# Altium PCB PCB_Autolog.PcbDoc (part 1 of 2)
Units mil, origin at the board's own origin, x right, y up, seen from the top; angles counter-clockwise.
Board outline 3847.36 x 2641.73 mil, 2 copper layers (Top Layer, Bottom Layer); 80 components, 62 nets, 278 pads, 180 vias.
Unrouted connection lines stored in the file: 64.
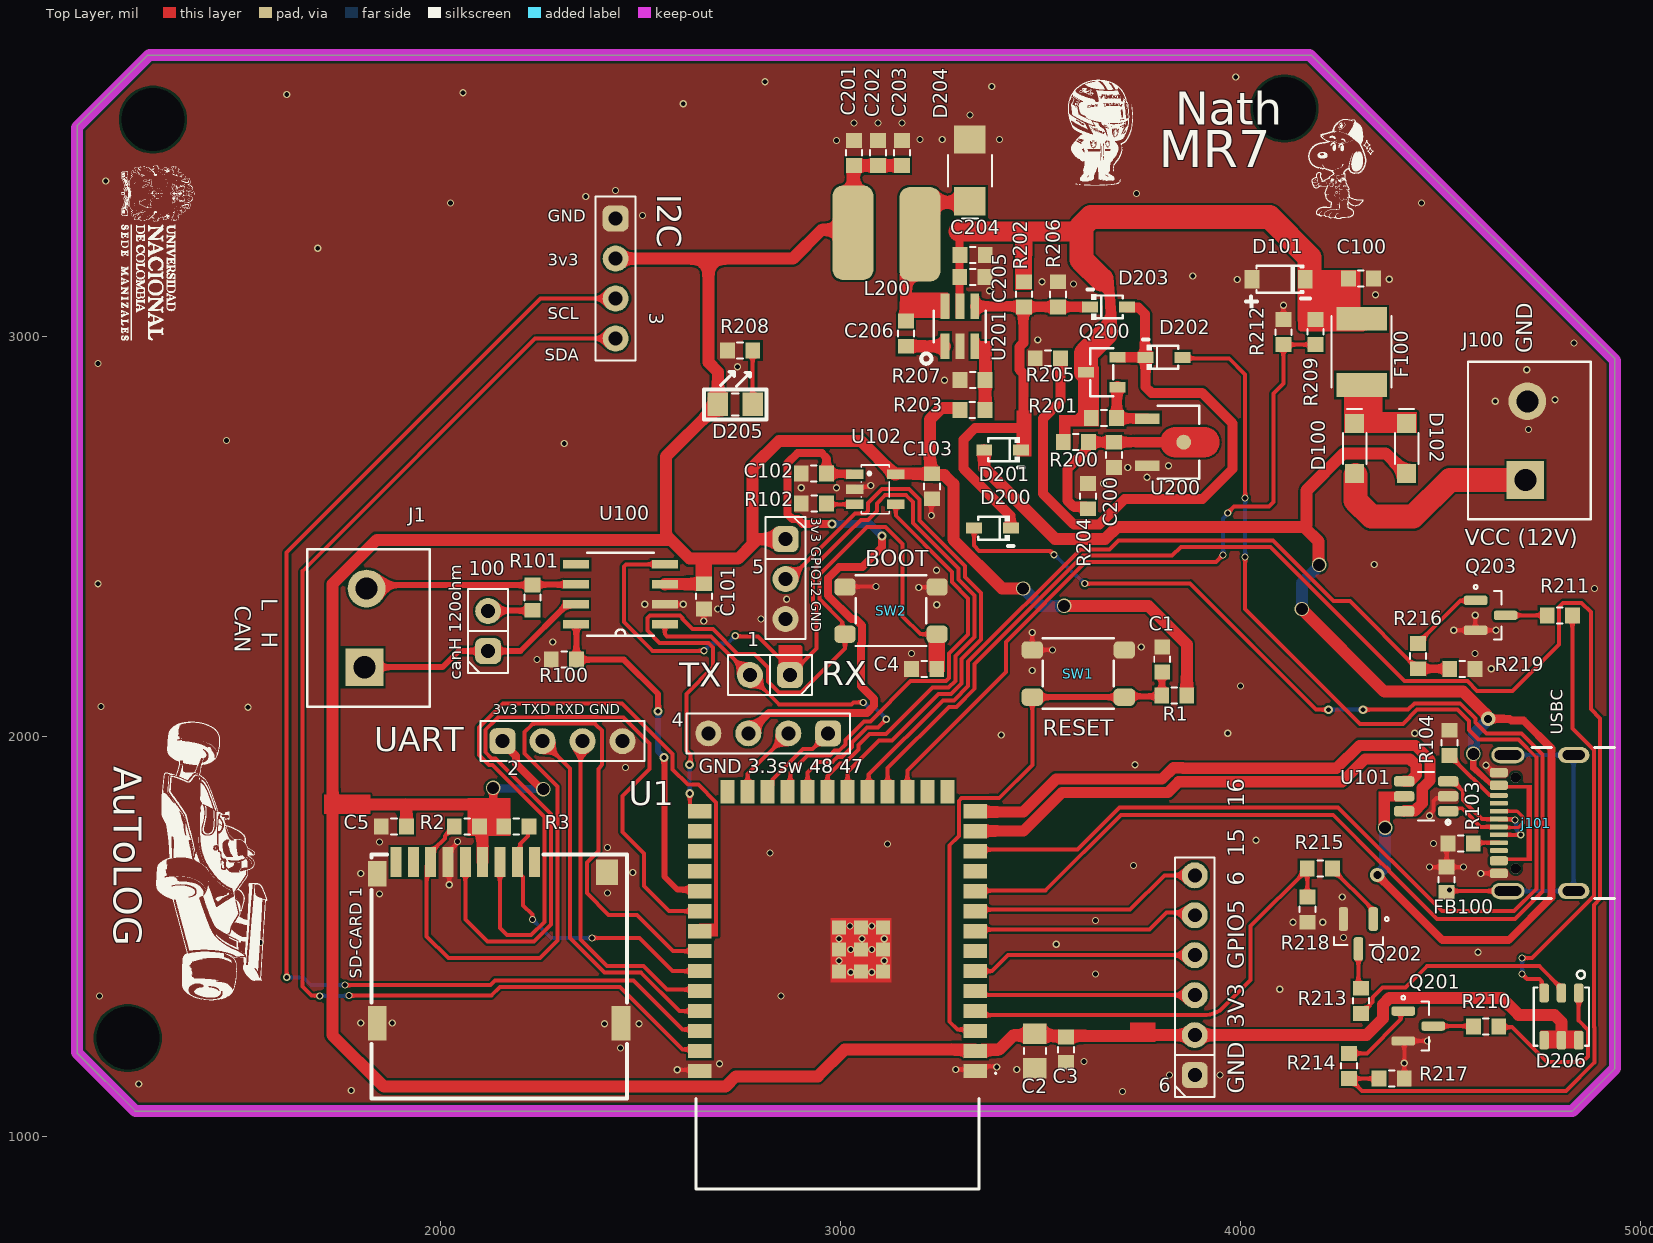
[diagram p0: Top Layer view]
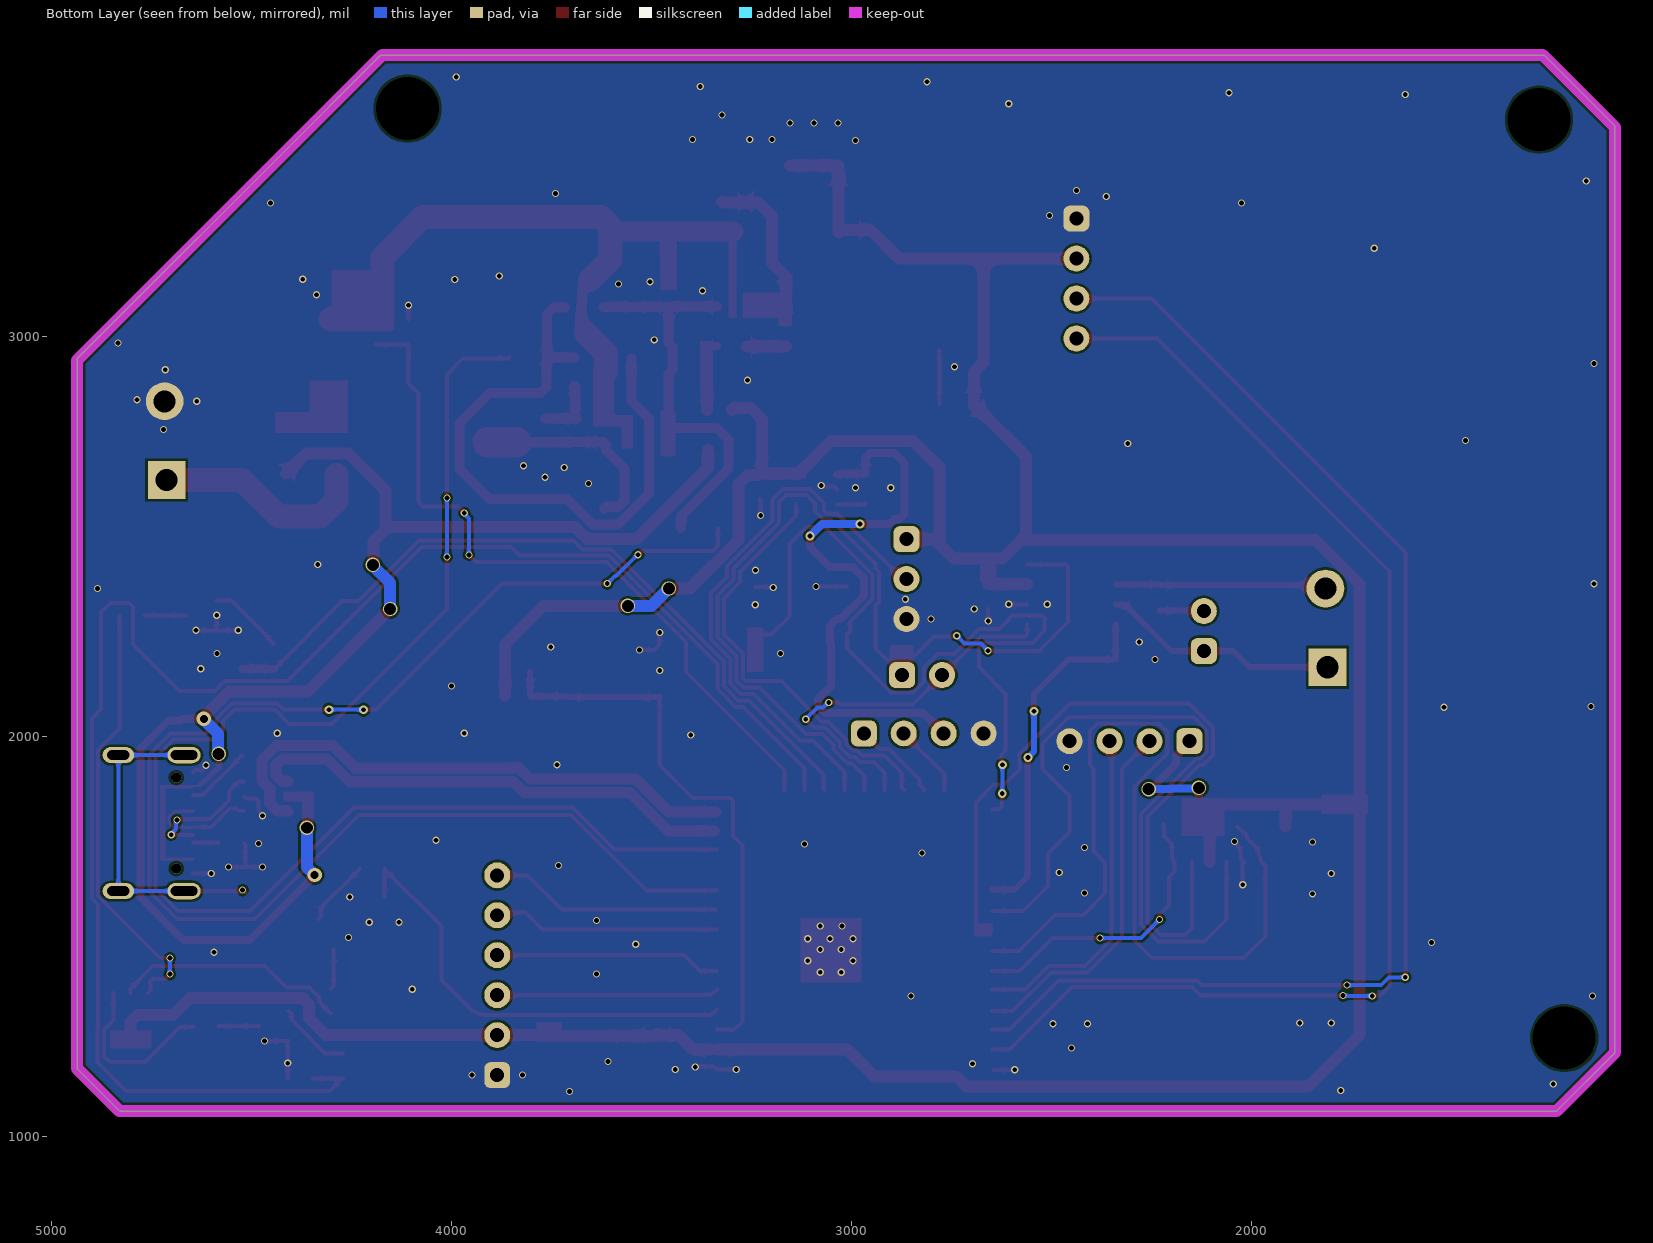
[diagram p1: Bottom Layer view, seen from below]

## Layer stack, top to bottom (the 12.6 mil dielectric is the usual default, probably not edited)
Top Solder: solder mask 0.4, Solder Resist, Dk 3.5
Top Layer: signal copper 1.4
Dielectric 1: dielectric 12.6, FR-4, Dk 4.8
Bottom Layer: signal copper 1.4
Bottom Solder: solder mask 0.4, Solder Resist, Dk 3.5

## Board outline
1089.65,1209.01 1235.67,1062.99 4830.71,1062.99 4937.01,1169.29 4937.01,2944.88 4826.77,3055.12 4437.01,3444.88 4177.17,3704.72 1266.95,3704.72 1089.65,3527.42

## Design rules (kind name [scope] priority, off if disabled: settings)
Clearance Clearance_1 [All] p1: gap=6 ignorepadtopadclearanceinfootprint=FALSE
Clearance Clearance_Vias [isvia] p2: gap=0 ignorepadtopadclearanceinfootprint=FALSE
DiffPairsRouting [All] p1: maxlimit=6 minlimit=6 mostfreqgap=6 toplayer_minwidth=10 toplayer_maxwidth=28 toplayer_prefwidth=28 bottomlayer_minwidth=10 bottomlayer_maxwidth=28 bottomlayer_prefwidth=28 maxuncoupledlength=500
HoleSize [All] p1: absolutevalues=TRUE maxlimit=200 minlimit=12 maxpercent=80.000 minpercent=20.000
MinimumAnnularRing [All] p1: minimumring=3
MinimumSolderMaskSliver [All] p1: minsoldermaskwidth=4
PlaneConnect [All] p1: planeconnectstyle=Direct reliefexpansion=20 reliefentries=4 reliefconductorwidth=10 reliefairgap=10
PolygonConnect [All] p1: connectstyle=Direct reliefconductorwidth=8 reliefentries=4 polygonreliefangle="90 Angle" airgapwidth=6
RoutingVias [All] p1: holewidth=12 width=22 viastyle="Through Hole" minholewidth=12 minwidth=18 maxholewidth=30 maxwidth=40
SilkToSilkClearance [All] p1: silktosilkclearance=2
SilkToSolderMaskClearance [IsPad] p1: minsilkscreentomaskgap=0.1 clearancetoexposedcopper=TRUE
SolderMaskExpansion SolderMaskExpansion_via [IsVia] p1: expansion=2 istentingtop=TRUE
SolderMaskExpansion [All] p2: expansion=2 istentingtop=FALSE
SupplyNets "Schematic Supply Nets_2" [InNet('3V3')] p1: voltage=0.000
SupplyNets "Schematic Supply Nets_1" [InNet('VCC')] p2: voltage=0.000
SupplyNets "Schematic Supply Nets" [InNet('GND')] p3: voltage=0.000
Width "Width3V3 o 5V" [InNet('3V3') OR InNet('VBUSS')] p1: maxlimit=30 minlimit=20 preferedwidth=30
Width Width_POWER [InNet('VCC')] p2: maxlimit=60 minlimit=20 preferedwidth=60
Width Width_1 [All] p3: maxlimit=100 minlimit=6 preferedwidth=10 minimp=50.000000 maximp=50.000000 favimp=50.000000
24 further rules are at their usual default settings.

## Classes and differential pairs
differential pair USBC: +USBC_P -USBC_N
differential pair USB_D: +USB_D_P -USB_D_N

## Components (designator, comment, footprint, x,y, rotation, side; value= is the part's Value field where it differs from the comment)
1 "2x1" H_2x1_TH_100mil 2822.83,2153.54 r180 top
2 "4x1" H_4x1_TH_2.54mm 2304.33,1988.19 r0 top
3 "4x1" H_4x1_TH_2.54mm 2437.01,3145.67 r270 top
4 "4x1" H_4x1_TH_2.54mm 2818.9,2007.87 r180 top
5 "3x1" H_3X1_TH_100mil 2862.2,2393.7 r270 top
6 "6x1" H_6x1_TH_100mil 3885.83,1402.76 r90 top
100 "2x1" H_2x1_TH_100mil 2118.11,2263.78 r90 top
C1 "1uF 50V" 0603_cap 3804.49,2192.48 r90 top value=1uF
C2 "22uF 16V" 0805_cap 3486,1212.93 r270 top value=22uF
C3 "0.1uF 50V" 0603_cap 3564.1,1216.54 r270 top value=0.1uF
C4 "0.1uF 50V" 0603_cap 3208.66,2169.29 r0 top value=0.1uF
C5 "10uF 10V" 0603_cap 1882.07,1774.6 r0 top value=10uF
C100 "0.1uF 50V" 0603_cap 4301.65,3145.67 r180 top value=0.1uF
C101 "0.1uF 50V" 0603_cap 2657.48,2350.4 r90 top value=0.1uF
C102 "22uF 10V" 0603_cap 2933.07,2657.48 r180 top value=22uF
C103 "22uF 10V" 0603_cap 3228.35,2625.98 r270 top value=22uF
C200 "1uF 50V" 0603_cap 3683.27,2704.72 r270 top value=1uF
C201 "22uF 10V" 0603_cap 3033.27,3459.72 r90 top value=22uF
C202 "22uF 10V" 0603_cap 3093.27,3459.72 r90 top value=22uF
C203 "22uF 10V" 0603_cap 3153.27,3459.72 r90 top value=22uF
C204 "1uF 50V" 0603_cap 3330,3205 r0 top value=1uF
C205 "1uF 50V" 0603_cap 3329.5,3149 r0 top value=1uF
C206 "0.1uF 50V" 0603_cap 3163.27,3007.72 r90 top value=0.1uF
D100 "40V 1A" SOD_123 4285.9,2720.47 r270 top
D101 "TVS_DIODE_SMF30A" TVS_DIODE_SMF30A 4095.63,3143.89 r180 top
D102 "40V 1A" SOD_123 4415.82,2720.47 r270 top
D200 "1N4148WS" SOD-323_1N4148 3379.9,2521 r180 top
D201 "1N4148WS" SOD-323_1N4148 3405.07,2717.28 r180 top
D202 "1N4148WS" SOD-323_1N4148 3808.85,2948.62 r0 top
D203 "1N4148WS" SOD-323_1N4148 3669.92,3074.72 r0 top
D204 "30V 3A" SMA 3323.27,3416.22 r90 top
D205 "2.9V" 0805_LED 2736.22,2830.71 r0 top
D206 "RGB" RGB_NS_3.5X3.7 4803.15,1299.21 r270 top
F100 "PTC_MF-MSMF110/16-2" FUSER_MF-MSMF110/16-2 4303.21,2962 r270 top
FB100 "60OHM 2A" 0603_fb 4515.75,1641.73 r270 top value="60 OHM"
J1 "CAN" CON_2x1_TH_5MM 1818.9,2271.65 r90 top
J100 "POWER" CON_2x1_TH_5MM 4722.91,2740.16 r90 top
j101 "USB C" CON_USB_C_16P_RA 4740.16,1783.46 r90 top
L200 "10uH 1.42A" Ind_5.8*5.2_NS 3114.61,3258.32 r180 top value=10uH
Q200 "SS8050" "SOT-23-3_TRANS NPN" 3653.27,2911.22 r0 top
Q201 "N CH" SOT_23_3 4444.88,1275.59 r0 top
Q202 "N CH" SOT_23_3 4295.28,1505.91 r270 top
Q203 "N CH" SOT_23_3 4625.98,2303.15 r0 top
R1 "10k 1/10W" 0603_res 3834.49,2102.48 r0 top value=10k
R2 "10k 1/10W" 0603_res 2064.96,1774.6 r0 top value=10k
R3 "10k 1/10W" 0603_res 2188.73,1774.6 r180 top value=10k
R100 "10k 1/10W" 0603_res 2307.48,2192.21 r0 top value=10k
R101 "120R 1/10W" 0603_res 2228.98,2347.21 r90 top value=120R
R102 "10k 1/10W" 0603_res 2933.07,2582.68 r0 top value=10k
R103 "5k1 1/10W" 0603_res 4551.18,1732.28 r0 top value=5k1
R104 "5k1 1/10W" 0603_res 4523.62,1984.25 r90 top value=5k1
R200 "226k 1/10W" 0603_res 3588.27,2736.22 r180 top value=226k
R201 "49k9 1/10W" 0603_res 3658.27,2796.22 r0 top value=49k9
R202 "0R 1/10W" 0603_res 3458.27,3106.22 r90 top value=0R
R203 "33k2 1/10W" 0603_res 3329.77,2816.22 r180 top value=33k2
R204 "73k2 1/10W" 0603_res 3618.27,2601.22 r270 top value=73k2
R205 "10k 1/10W" 0603_res 3518.27,2946.22 r0 top value=10k
R206 "10k 1/10W" 0603_res 3543.27,3106.22 r270 top value=10k
R207 "10k 1/10W" 0603_res 3329.77,2891.22 r0 top value=10k
R208 "84R5 1/10W" 0603_res 2748.65,2965.7 r180 top value=84R5
R209 "49k9 1/10W" 0603_res 4187.48,3011.81 r90 top value=49k9
R210 "120R 1/10W" 0603_res 4614.76,1274.17 r180 top value=120R
R211 "120R 1/10W" 0603_res 4799.21,2303.15 r180 top value=120R
R212 "10k 1/10W" 0603_res 4107.48,3011.81 r270 top value=10k
R213 "100R 1/10W" 0603_res 4301.18,1338.58 r90 top value=100R
R214 "1k 1/10W" 0603_res 4272.24,1175.75 r90 top value=1k
R215 "1k 1/10W" 0603_res 4198.82,1669.29 r0 top value=1k
R216 "1k 1/10W" 0603_res 4444.88,2200.79 r90 top value=1k
R217 "10k 1/10W" 0603_res 4378.54,1144.25 r0 top value=10k
R218 "10k 1/10W" 0603_res 4167.32,1566.93 r90 top value=10k
R219 "10k 1/10W" 0603_res 4555.12,2169.29 r180 top value=10k
"SD-CARD 1" "Micro_SD_socket" "MICROSD CARD SMD" 2145.67,1484.25 r0 top
SW1 "RESET" Sw_PUSH_4.5x4.5x5mm 3594.49,2157.48 r180 top
SW2 "BOOT" Sw_PUSH_4.5x4.5x5mm 3125.98,2314.96 r180 top
U1 "ESP32-S3-WROOM-1-N16R8" ESP32S3WROOM1N8R2 3053.13,1358.02 r0 top
U100 "CAN Transceiver" D8-M 2448.98,2355.71 r180 top
U101 "USBLC6-2SC6" SOT_23_6 4464.57,1850.39 r180 top
U102 "MT9700" SOT-23-5_L3.0-W1.7-P0.95-LS2.8-BR 3086.61,2618.11 r180 top
U200 "HT7033A-1_sensadoV" SOT-89-3_L4.5-W2.5-P1.50-LS4.2-BR 3820.23,2736.21 r180 top
U201 "LMR14006 Buck 40V 600mA" DDC6_TEX-M 3298.27,3026.22 r90 top

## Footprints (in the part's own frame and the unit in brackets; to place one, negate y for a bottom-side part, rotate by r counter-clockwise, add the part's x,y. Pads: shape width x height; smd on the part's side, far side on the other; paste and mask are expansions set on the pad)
0603_cap [mil]
  rect 37x40 smd: 1(-31.5,0) 2(31.5,0)
  silkscreen extent -7,-20 8,20, body extent -31,-17 31,17, height 34
0603_fb [mil]
  rect 37x40 smd: 1(-31.5,0) 2(31.5,0)
  silkscreen extent -7,-20 8,20, body extent -32,-16 31,16, height 32
0603_res [mil] "1608 Metric / 20190225 / C-A.Serna.A"
  rect 37x40 smd: 1(-31.5,0) 2(31.5,0)
  silkscreen extent -6,-20 8,20, body extent -31,-16 32,16, height 12
0805_cap [mm]
  rect 1.3x1.5 smd: 1(-1.1,0) 2(1.1,0)
  silkscreen extent -0.2,-0.7 0.2,0.7, body extent -1.13,-0.7 1.07,0.7, height 1
0805_LED [mm]
  rect 1.3x1.5 smd: 1(-1.1,0) 2(1.1,0)
  silkscreen extent -1.98,-0.97 1.98,2.07, body extent -1,-0.62 1,0.63, height 1.1
CON_2x1_TH_5MM [mm]
  rect 2.4x2.4 hole 1.4: 1(-2.5,0.254)
  round 2.4 hole 1.4: 2(2.5,0.127)
  silkscreen extent -5,-3.9 5,3.9, body extent -5,-3.9 5,3.9, height 10.2
CON_USB_C_16P_RA [mm]
  oval 1x2 hole 0.6 slot 1.4 at 90 deg: 0(-4.32,-2.377) 0(4.32,-2.377)
  oval 1.05x2.1 hole 0.6 slot 1.7 at 90 deg: 0(-4.32,1.803) 0(4.32,1.803)
  rrect50% 0.6x1.15 smd mask+0.047: A1/B12(-3.2,2.378) A4/B9(-2.4,2.378) B1/A12(3.2,2.378) B4/A9(2.4,2.378)
  rrect50% 0.3x1.15 smd mask+0.047: A5(-1.25,2.378) A6(-0.25,2.378) A7(0.25,2.378) A8(1.25,2.378) B5(1.75,2.378) B6(0.75,2.378) B7(-0.75,2.378) B8(-1.75,2.378)
  round 0.65 hole 0.65 unplated mask+0.025: ""(-2.89,1.303) ""(2.89,1.303)
  silkscreen extent -4.79,-4.98 4.79,0.27, body extent -4.79,-4.98 4.79,2.73, height 3.31
D8-M [mil]
  rect 65.5x22 smd paste+0: 1(-111.25,75) 2(-111.25,25) 3(-111.25,-25) 4(-111.25,-75) 5(111.25,-75) 6(111.25,-25) 7(111.25,25) 8(111.25,75)
  silkscreen extent -84,-104 84,104, body extent -122,-99 122,99, height 69
DDC6_TEX-M [mm]
  rect 1.61x0.558 smd paste+0: 1(-1.269,0.95) 2(-1.269,0) 3(-1.269,-0.95) 4(1.269,-0.95) 5(1.269,0) 6(1.269,0.95)
  silkscreen extent -2.38,-1.65 1,2.46, body extent -1.52,-1.52 1.52,1.52, height 1.7
ESP32S3WROOM1N8R2 [mm]
  rect 1.5x0.9 smd: 1(7.201,-4.955) 2(7.201,-3.685) 3(7.201,-2.415) 4(7.201,-1.145) 5(7.201,0.125) 6(7.201,1.395) 7(7.201,2.665) 8(7.201,3.935) 9(7.201,5.205) 10(7.201,6.475) 11(7.201,7.745) 12(7.201,9.015) 13(7.201,10.285) 14(7.201,11.555) 27(-10.299,11.555) 28(-10.299,10.285) 29(-10.299,9.015) 30(-10.299,7.745) 31(-10.299,6.475) 32(-10.299,5.205) 33(-10.299,3.935) 34(-10.299,2.665) 35(-10.299,1.395) 36(-10.299,0.125) 37(-10.299,-1.145) 38(-10.299,-2.415) 39(-10.299,-3.685) 40(-10.299,-4.955)
  rect 0.9x1.5 smd: 15(5.436,12.805) 16(4.166,12.805) 17(2.896,12.805) 18(1.626,12.805) 19(0.356,12.805) 20(-0.914,12.805) 21(-2.184,12.805) 22(-3.454,12.805) 23(-4.724,12.805) 24(-5.994,12.805) 25(-7.264,12.805) 26(-8.534,12.805)
  rect 0.9x0.9 smd: 41(-0.049,2.765) 42(-0.049,1.365) 43(1.351,1.365) 44(1.351,2.765) 45(1.351,4.165) 46(-0.049,4.165) 47(-1.449,4.165) 48(-1.449,2.765) 49(-1.449,1.365)
  silkscreen extent -10.55,-12.45 8.55,-5.05, body extent -10.55,-12.45 7.45,13.05, height 3.25
FUSER_MF-MSMF110/16-2 [mm]
  rect 1.5x3.2 smd: 1(-2.1,0) 2(2.1,0)
  silkscreen extent -2.27,-1.91 2.27,1.91, body extent -2.27,-1.62 2.27,1.62, height 0.85
H_2x1_TH_100mil [mil]
  rrect50% 65x65 hole 35: 1(-50,0)
  round 65 hole 35: 2(50,0)
  silkscreen extent -105,-50 105,50, body extent -101,-49 99,49, height 339
H_3X1_TH_100mil [mil]
  rrect50% 65x65 hole 35: 1(-100,0)
  round 65 hole 35: 2(0,0) 3(100,0)
  silkscreen extent -155,-50 150,50, body extent -142,-46 142,46, height 320
H_4x1_TH_2.54mm [mil]
  rrect50% 65x65 hole 35: 1(-150,0)
  round 65 hole 35: 2(-50,0) 3(50,0) 4(150,0)
  silkscreen extent -205,-50 205,50, body extent -200,-50 205,50, height 420
H_6x1_TH_100mil [mil]
  rrect50% 65x65 hole 35: 1(-250,0)
  round 65 hole 35: 2(-150,0) 3(-50,0) 4(50,0) 5(150,0) 6(250,0)
  silkscreen extent -305,-50 295,50
Ind_5.8*5.2_NS [mm]
  rrect50% 2.6x6 smd: 1(-2.125,0.053) 2(2.125,-0.053)
  body extent -3,-2.75 3,2.75, height 4.5
"MICROSD CARD SMD" [mm]
  rect 0.7x1.9 smd: 1(2.25,5.125) 2(1.15,5.125) 3(0.05,5.125) 4(-1.05,5.125) 5(-2.15,5.125) 6(-3.25,5.125) 7(-4.35,5.125) 8(-5.45,5.125) 9(-6.55,5.125)
  rect 1.2x1.6 smd: 10(-7.75,4.375)
  rect 1.2x2.2 smd: 11(-7.75,-5.125) 12(7.75,-5.125)
  rect 1.4x1.6 smd: 13(6.85,4.475)
  silkscreen extent -8.13,-9.91 8.13,5.59, body extent -8.08,-9.41 8.02,5.6, height 1.9
RGB_NS_3.5X3.7 [mm]
  rrect50% 1.2x0.6 smd: 1(-1.5,1.1) 2(-1.5,0) 3(-1.5,-1.1) 4(1.5,-1.1) 5(1.5,0) 6(1.5,1.1)
  silkscreen extent -2.92,-1.75 1.85,1.75, body extent -1.85,-1.74 1.85,1.75, height 1
SMA [mm]
  rect 1.8x2 smd: 1(-1.965,0) 2(1.965,0)
  silkscreen extent -3.05,-1.4 0.98,1.4, body extent -2.64,-1.4 2.64,1.4, height 2.34
SOD-323_1N4148 [mm]
  rect 1x0.7 smd: 1(-1.172,0) 2(1.172,0)
  silkscreen extent -1.32,-0.8 0.9,1.12, body extent -1.22,-0.69 1.28,0.56, height 1.1
SOD_123 [mm]
  rect 1.2x1.2 smd: 1(-1.6,0) 2(1.6,0)
  silkscreen extent -2.5,-0.75 1,0.75, body extent -1.93,-0.8 1.77,0.8, height 1.28
"SOT-23-3_TRANS NPN" [mm]
  rect 1x0.65 smd: 1(1,-0.95) 2(1,0.95) 3(-1,0)
  silkscreen extent -0.73,-1.53 0.73,1.53, body extent -1.17,-1.45 1.23,1.45, height 1.11
SOT-23-5_L3.0-W1.7-P0.95-LS2.8-BR [mm]
  rect 1.1x0.6 smd: 1(1.3,-0.95) 2(1.3,0) 3(1.3,0.95) 4(-1.3,0.95) 5(-1.3,-0.95)
  silkscreen extent -0.9,-1.55 0.9,1.55, body extent -0.93,-1.5 0.88,1.55, height 1
SOT-89-3_L4.5-W2.5-P1.50-LS4.2-BR [mm]
  rect 1.575x0.672 smd paste+0 mask+0.051: 1(1.356,-1.5) 3(1.356,1.5)
  round 0.95 smd: 2(-0.966,0)
  Top Layer region: -2.283,0.95 -0.429,0.95 -0.384,0.949 -0.34,0.946 -0.296,0.94 -0.252,0.933 -0.208,0.924 -0.165,0.912 -0.123,0.899 -0.081,0.884 -0.04,0.866 0,0.847 0.04,0.826 0.078,0.803 0.115,0.779 0.151,0.752 0.185,0.724 0.219,0.695 0.251,0.664 0.281,0.631 0.31,0.597 0.337,0.562 0.362,0.525 0.386,0.488 0.408,0.449 0.428,0.409 0.447,0.33 2.144,0.33 2.144,-0.33 0.447,-0.33 0.428,-0.409 0.408,-0.449 0.386,-0.488 0.362,-0.526 0.337,-0.562 0.31,-0.597 0.281,-0.631 0.251,-0.664 0.219,-0.695 0.185,-0.725 0.151,-0.753 0.115,-0.779 0.078,-0.804 0.04,-0.827 0,-0.848 -0.04,-0.867 -0.081,-0.884 -0.123,-0.899 -0.165,-0.913 -0.208,-0.924 -0.252,-0.934 -0.296,-0.941 -0.34,-0.946 -0.384,-0.949 -0.429,-0.95 -2.283,-0.95 -2.328,-0.949 -2.372,-0.946 -2.416,-0.941 -2.46,-0.934 -2.504,-0.924 -2.547,-0.913 -2.589,-0.899 -2.631,-0.884 -2.672,-0.867 -2.713,-0.848 -2.752,-0.827 -2.79,-0.804 -2.827,-0.779 -2.863,-0.753 -2.898,-0.725 -2.931,-0.695 -2.963,-0.664 -2.993,-0.631 -3.022,-0.597 -3.049,-0.562 -3.075,-0.526 -3.098,-0.488 -3.12,-0.449 -3.141,-0.409 -3.159,-0.369 -3.175,-0.327 -3.189,-0.285 -3.202,-0.242 -3.212,-0.199 -3.22,-0.155 -3.227,-0.111 -3.231,-0.067 -3.233,-0.022 -3.233,0.022 -3.231,0.067 -3.227,0.111 -3.22,0.155 -3.212,0.199 -3.202,0.242 -3.189,0.285 -3.175,0.327 -3.159,0.369 -3.141,0.409 -3.12,0.449 -3.098,0.488 -3.075,0.525 -3.049,0.562 -3.022,0.597 -2.993,0.631 -2.963,0.664 -2.931,0.695 -2.898,0.724 -2.863,0.752 -2.827,0.779 -2.79,0.803 -2.752,0.826 -2.713,0.847 -2.672,0.866 -2.631,0.884 -2.589,0.899 -2.547,0.912 -2.504,0.924 -2.46,0.933 -2.416,0.94 -2.372,0.946 -2.328,0.949 -2.283,0.95
  silkscreen extent -1.95,-2.33 0.7,2.33, body extent -1.94,-2.34 1.09,2.34, height 1
SOT_23_3 [mm]
  rrect50% 1.5x0.6 smd: 1(-0.95,0.95) 2(-0.95,-0.95) 3(0.95,0)
  silkscreen extent -1.07,-1.55 0.7,1.92, body extent -0.7,-1.52 0.7,1.53, height 1.12
SOT_23_6 [mm]
  rrect50% 1.3x0.65 smd: 1(-1.4,0.95) 2(-1.4,0) 3(-1.4,-0.95) 4(1.4,-0.95) 5(1.4,0) 6(1.4,0.95)
  silkscreen extent -1.52,-1.55 0.5,1.78, body extent -1.5,-1.45 1.3,1.45, height 1.45
Sw_PUSH_4.5x4.5x5mm [mm]
  rrect50% 1.35x1.1 smd: 1(-2.925,1.5) 1(2.925,1.5) 2(-2.925,-1.5) 2(2.925,-1.5)
  silkscreen extent -2.25,-2.25 2.25,2.25, body extent -2.25,-2.25 2.25,2.25, height 5
TVS_DIODE_SMF30A [mm]
  rect 0.95x1.15 smd: 1(-1.692,0) 2(1.692,0)
  silkscreen extent -2.01,-0.87 2.08,1.78, body extent -1.85,-0.89 1.85,0.91, height 1.55

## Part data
1 100: library part H_Male_2x1_TH_100mil, "H_Male_2x1_TH_100mil"
2 3 4: library part H_Male_4x1_TH_100mil, "H_Male_4x1_TH_100mil"
5: library part H_Male_3x1_TH_100mil, "H_Male_3x1_TH_100mil"
6: library part H_Male_6x1_TH_100mil, "H_Male_6x1_TH_100mil"
C1 C200 C204 C205: library part Cap_1uF_0603_50V, "50V 1uF X5R ±10% 0603 Multilayer Ceramic Capacitors MLCC - SMD/SMT ROHS", Manufacturer="Samsung Electro-Mechanics", Manufacturer Part Number=CL10A105KB8NNNC, Supplier Part Number 1=C15849
C2: library part Cap_22uF_0805_16V, "16V 22uF X5R ±20% 0805 Multilayer Ceramic Capacitors MLCC - SMD/SMT ROHS", Manufacturer=Chinocera, Manufacturer Part Number=HGC0805R5226M160NSLJ, Supplier Part Number 1=C33546008
C3 C4 C100 C101 C206: library part Cap_0.1uF_0603_50V, "50V 100nF Y5V -20%~+80% 0603 Multilayer Ceramic Capacitors MLCC - SMD/SMT ROHS", Manufacturer="Walsin Tech Corp", Manufacturer Part Number=0603F104Z500CT, Supplier Part Number 1=C83060
C5: library part Cap_10uF_0603_10V, "10V 10uF X5R ±10% 0603 Multilayer Ceramic Capacitors MLCC - SMD/SMT ROHS", Manufacturer=CCTC, Manufacturer Part Number=TCC0603X5R106K100CT, Supplier Part Number 1=C380314
C102 C103 C201 C202 C203: library part Cap_22uF_0603_10V, "10V 22uF X5R ±20% 0603 Multilayer Ceramic Capacitors MLCC - SMD/SMT ROHS", Manufacturer=HRE, Manufacturer Part Number=CGA0603X5R226M100JT, Supplier Part Number 1=C6119863
D100 D102: library part D_Schottky_40V_1A_SOD_123F, "DIODE SCHOTTKY 40V 1A SOD123F", Manufacturer="Shanghai Prisemi Elec", Manufacturer Part Number=PSBD1DF40V1H, Supplier Part Number 1=C110730
D101: "TVS DIODE 30VWM 48.4VC SOD123F", Manufacturer="Diotec Semiconductor", Manufacturer Part Number=SMF30A, Supplier Part Number 1=4878-SMF30ATR-ND
D200 D201 D202 D203: library part 1N4148WS_DIODE, "DIODE GP 100V 150mA SOD-323", Manufacturer=JSCJ, Supplier Part Number 1=C2128
D204: library part D_Schottky_40V_3A_SMA, "40V Independent 3A 550mV@3A SMA Schottky Diodes ROHS", Manufacturer=TDSEMIC, Manufacturer Part Number=SS34-TD, Supplier Part Number 1=C46550832
D205: library part LED_0805_Green, "LED GREEN CLEAR 0805 SMD", Manufacturer=XINGLIGHT, Manufacturer Part Number=XL-2012UGC, Supplier Part Number 1=C965815
D206: library part LED_RGB_3535_SMD, "-30℃~+85℃ RGB 110° 3535(mm) Light Emitting Diodes (LED) ROHS", Manufacturer="Foshan NationStar Optoelectronics", Manufacturer Part Number=RS-3535MWAM, Supplier Part Number 1=C842778
F100: "Polymeric PTC Resettable Fuse 16V 1.1 A Ih Surface Mount 1812 (4532 Metric), Concave", Manufacturer="Bourns Inc.", Manufacturer Part Number=MF-MSMF110/16-2, Supplier Part Number 1=MF-MSMF110/16-2TR-ND
FB100: library part FB_60_0603_2A, "2A 1 100mΩ 60Ω@100MHz ±25% 0603 Ferrite Beads ROHS", Manufacturer=TAI-TECH, Manufacturer Part Number=HCB1608KF-600T20, Supplier Part Number 1=C369516
J1 J100: library part Con_2x1_TH_5mm, "2POS 5MM", Manufacturer=JILN, Manufacturer Part Number=JL126-50002G01, Supplier Part Number 1=C394556
j101: library part CON_USB_TYPEC_16P, "3A USB 3.1 1 Surface Mount 16P Female -40℃~+85℃ Type-C SMD USB Connectors ROHS", Manufacturer="SHOU HAN", Manufacturer Part Number=TYPE-C-3.1-16PIN, Supplier Part Number 1=C7507405
L200: library part Inductor_10uH_1.42A_5.8*5.2mm, "1.42A 10uH ±10% 87.9mΩ SMD,5.8x5.2mm Inductors (SMD) ROHS", Manufacturer="SHOU HAN", Manufacturer Part Number=CY54-10UH, Supplier Part Number 1=C2929431
Q200: library part TRANS_NPN_SS8050_SOT23, "SS8050 Transistor BJT NPN 40V 1.5A", Manufacturer=JSCJ, Manufacturer Part Number=SS8050(RANGE:200-350), Supplier Part Number 1=C2150
Q201 Q202 Q203: library part Q_NFET_20V_3.2A_SOT23, "MOSFET N-CH 20V SOT23", Manufacturer=Doeshare, Manufacturer Part Number=DN2302S, Supplier Part Number 1=C2931750
R1 R2 R3 R100 R102 R205 R206 R207 R212 R217 R218 R219: library part Res_10k_0603_1/10W, "RES SMD 10k OHM 5% 1/10W 0603", Manufacturer=FOJAN, Manufacturer Part Number=FRC0603J103TS, Supplier Part Number 1=C2930027
R101 R210 R211: library part Res_120R_0603_1/10W, "100mW Thick Film Resistor 75V ±100ppm/℃ ±1% 120Ω 0603 Chip Resistor - Surface Mount ROHS", Manufacturer=FOJAN, Manufacturer Part Number=FRC0603F1200TS, Supplier Part Number 1=C2906988
R103 R104: library part Res_5k1_0603, "RES 5.1kΩ ±1% 100mW 0603", Manufacturer=YAGEO, Manufacturer Part Number=RC0603FR-0773K2L, Supplier Part Number 1=C163420
R200: library part Res_226k_0603_1/10W, "100mW Thick Film Resistors 75V ±100ppm/℃ ±1% 226kΩ 0603 Chip Resistor - Surface Mount ROHS", Manufacturer=YAGEO, Manufacturer Part Number=RC0603FR-07226KL, Supplier Part Number 1=C165744
R201 R209: library part Res_49k9_0603_1/10W, "100mW Thick Film Resistor 75V ±100ppm/℃ ±1% 49.9kΩ 0603 Chip Resistor - Surface Mount ROHS", Manufacturer=YAGEO, Manufacturer Part Number=RC0603FR-0749K9L, Supplier Part Number 1=C114624
R202: library part Res_0R_0603_1/10W, "RES SMD 0R OHM 5% 1/10W 0603", Manufacturer=FOJAN, Manufacturer Part Number="FRC0603P000 TS", Supplier Part Number 1=C2907080
R203: library part Res_33k2_0603_1/10W, "100mW Thick Film Resistor 75V ±100ppm/℃ ±1% 33.2kΩ 0603 Chip Resistor - Surface Mount ROHS", Manufacturer=YAGEO, Manufacturer Part Number=RC0603FR-0733K2L, Supplier Part Number 1=C185338
R204: library part Res_73k2_0603_1/10W, "100mW Thick Film Resistor 75V ±100ppm/℃ ±1% 73.2kΩ 0603 Chip Resistor - Surface Mount ROHS", Manufacturer=YAGEO, Manufacturer Part Number=RC0603FR-0773K2L, Supplier Part Number 1=C163420
R208: library part Res_84R5_0603_1/10W, "100mW Thick Film Resistor 50V ±100ppm/℃ ±1% 84.5Ω 0603 Chip Resistor - Surface Mount ROHS", Manufacturer="LIZ Elec", Manufacturer Part Number=CR0603FA84R5G, Supplier Part Number 1=C101216
R213: library part Res_100R_0603_1/10W, "RES SMD 100R OHM 5% 1/10W 0603", Manufacturer=FOJAN, Manufacturer Part Number="FRC0603J101 TS", Supplier Part Number 1=C2907089
R214 R215 R216: library part Res_1k_0603_1/10W, "RES SMD 1k OHM 5% 1/10W 0603", Manufacturer=FOJAN, Manufacturer Part Number="FRC0603J102 TS", Supplier Part Number 1=C2907113
"SD-CARD 1": "CONN MICROSD CARD R/A SMD", Manufacturer=ATOM, Manufacturer Part Number=MR01A-01211, Supplier Part Number 1=C479742
SW1 SW2: library part Sw_PUSH_4.5x4.5x5.0xmm, "SWITCH TACTILE SPST-NO 0.05A 12V", Manufacturer=BZCN, Manufacturer Part Number=TSC015A05026A, Supplier Part Number 1=C2888509
U1: library part "ESP32-S3-WROOM-1-N16R8  nnnnn", "ESP32-S3 Wi-Fi & Bluetooth 5 MCU module, 16MB Flash, 8MB PSRAM.", Manufacturer="Espressif Systems", Suplier  Part Number=5407-ESP32-S3-WROOM-1-N16R8TR-ND
U100: library part SN65HVD230DR-CAN, "Transceiver Half CANbus 8-SOIC", Manufacturer="Texas Instruments", Manufacturer product number=SN65HVD230DR, Suplier  Part Number=296-11654-2-ND
U101: library part TVS_5.25V_2CH_SOT_23_6, "TVS DIODE 5.25V 17V SOT23-6", Manufacturer=STMicroelectronics, Supplier Part Number 1=C7519
U102: "Switch de potencia con límite de corriente y control enable para corte en sleep de periféricos y MicroSD", Manufacturer="XI'AN Aerosemi Tech", Supplier Part Number 1=C89855
U200: library part "HOLTEK HT7033A-1_sensadoV", "Detector de tensión con umbral de 3.3V", Manufacturer=HOLTEK, Manufacturer product number=HT7033A-1, Suplier  Part Number=C73715
U201: library part LMR14006XDDCR, "IC REG BUCK ADJ 600MA SOT23", Manufacturer="Texas Instruments", Suplier  Part Number=296-44318-2-ND

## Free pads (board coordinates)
  round 60 hole 157.48 unplated: 0(1216.54,1245.48) 0(1279.53,3543.31) 0(4110.24,3570.87)

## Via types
v1: diameter 18, hole 12, Top Layer to Bottom Layer, tented both sides, 162 vias
v2: diameter 22, hole 12, Top Layer to Bottom Layer, tented both sides, 8 vias
v3: diameter 36, hole 30, Top Layer to Bottom Layer, tented both sides, 7 vias
v4: diameter 36, hole 20, Top Layer to Bottom Layer, tented both sides, 2 vias
v5: diameter 37, hole 30, Top Layer to Bottom Layer, tented both sides, 1 vias

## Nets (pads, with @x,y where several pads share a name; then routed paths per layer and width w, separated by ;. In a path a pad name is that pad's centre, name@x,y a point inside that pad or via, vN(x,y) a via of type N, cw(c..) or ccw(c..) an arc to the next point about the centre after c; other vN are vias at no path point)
3.3_SWITCHED: 4.3 C102.1 U102.1 | length 1524.5
  Top Layer w20: 4.3@2768.9,2007.87 2820.08,2059.06 3065.78,2059.06 3083.66,2076.93 3083.66,2093.5 3051.18,2125.98 3051.18,2231.75 3053.4,2233.97 3053.4,2277.84 3037.69,2293.56 3026.77,2293.56 2968.25,2352.08 2968.25,2395.95 2996.35,2424.05 3054,2424.05 3103.51,2473.56 v2(3103.51,2501.51) ; v2(2978.4,2531.5) 2904.92,2531.5 2892.64,2543.77 2879.34,2543.77 2867.07,2556.05 2867.07,2684.11 2891.62,2708.66 2952.85,2708.66 2964.57,2696.95 C102.1@2964.57,2657.48 3023.62,2657.48 3025.59,2655.51 U102.1@3035.43,2655.51
  Bottom Layer w20: v2(2978.4,2531.5) 3073.52,2531.5 v2(3103.51,2501.51)
3V3: 2.1 3.2 5.1 6.2 "SD-CARD 1.4" C2.1 C3.1 C5.2 C101.2 C103.1 C201.1 C202.1 C203.1 D205.1 D206.4 D206.5 D206.6 L200.2 R1.2 R2.2 R3.2 R203.2 U1.2 U100.3 U102.5 | length 10281.6
  Top Layer w20: 2106.3,1807.09 2109.82,1810.6 ; 2130.8,1810.6 2131,1810.8 2131,1863.72 2130.8,1863.91 v5(2130.8,1871.57) ; 2.1@2154.33,1988.19 2154.33,1984.81 2187.78,1951.36 2187.78,1931.78 2251.15,1868.41 v3(2256.35,1868.41)
  Top Layer w30: C5.2@1913.57,1774.6 1913.57,1828.24 1911.73,1830.09 ; R2.2@2087.74,1788.53 2104.33,1771.93 2104.33,1686.03 ; 2106.3,1807.09 2083.3,1830.09 1911.73,1830.09 ; 3.2@2437.01,3195.67 2669.29,3195.67 ; U100.3@2560.23,2380.71 2560.82,2381.31 2656.89,2381.31 C101.2@2657.48,2381.9 C101.2@2655.98,2381.9 ; 5.1@2862.2,2493.7 2792.15,2493.7 2781.11,2482.67 ; U102.5@3137.8,2655.51 3134.33,2655.51 3050.18,2739.66 2845.96,2739.66 2779.53,2673.23 2779.53,2484.25 2781.11,2482.67 ; U102.5@3144.45,2657.48 C103.1@3226.85,2657.48 ; C203.1@3153.27,3428.22 C202.1@3093.27,3428.22 C201.1@3033.27,3428.22 3032.11,3427.06 3032.11,3261.59 L200.2@3030.94,3260.43 3024.07,3267.3 2952.34,3267.3 2880.71,3195.67 2669.29,3195.67 ; C103.1@3223.35,2660.98 3223.35,2793.3 3252.34,2822.29 3277.19,2822.29 3278.27,2821.22 3294.77,2821.22 3298.27,2817.72 R203.2@3298.27,2816.22 ; C103.1@3228.35,2657.48 3231.85,2653.98 3259.4,2653.98 3281.94,2631.45 3281.94,2492.32 3404.18,2370.08 v3(3456.69,2370.08) ; U1.2@3336.61,1216.93 3010.11,1216.93 2942.78,1149.61 2737.54,1149.61 2712.14,1124.21 1857.12,1124.21 1728.35,1252.99 1728.35,1841.9 ; U1.2@3354.33,1216.54 3396.03,1216.54 3431.49,1251.99 3481.76,1251.99 C2.1@3486,1256.24 ; C2.1@3486,1251 3729.81,1251 3739.09,1260.28 3740.59,1260.28 3744.09,1263.78 ; v3(3559.06,2326.77) 3769.9,2326.77 3865.99,2230.68 R1.2@3865.99,2102.48 ; 3756.62,1252.76 6.2@3885.83,1252.76 4315.05,1252.76 4356.95,1294.66 4356.95,1330.04 4372.71,1345.8 4654.2,1345.8 4696.24,1303.76 4785.58,1303.76 4803.15,1286.18 D206.5@4803.15,1240.16 ; 1728.35,1841.9 1740.16,1830.09 1911.73,1830.09 ; 1728.35,1841.9 1728.35,2381.04 1839.43,2492.13 2574.8,2492.13 ; 2574.8,2492.13 2562.99,2503.94 2562.99,2700.79 2678.39,2816.18 2682.32,2816.18 2692.91,2826.77 D205.1@2692.91,2830.71 2692.91,2912.19 2669.29,2935.81 2669.29,3195.67 ; 2574.8,2492.13 2622.05,2444.88 2743.33,2444.88 2781.11,2482.67
  Bottom Layer w20: v5(2130.8,1871.57) 2132.56,1869.82 2198.35,1869.82 2199.75,1868.41 v3(2256.35,1868.41)
  Bottom Layer w30: v3(3456.69,2370.08) 3500,2326.77 v3(3559.06,2326.77)
BLUE_LED: R214.1 R217.1 U1.18 | length 4257.5
  Top Layer w10: U1.18@3117.13,1866.14 3117.41,1866.43 3117.41,1920.56 3271.14,2074.29 3289.73,2074.29 3334.84,2119.41 3334.84,2181.03 3606.03,2452.22 3829.37,2452.22 3851.47,2474.32 4074.8,2474.32 4410.83,2138.29 4568.2,2138.29 4592.31,2114.17 4681.1,2114.17 4797.21,2230.28 4797.21,2323.71 4807.65,2334.15 4853.77,2334.15 4876.95,2310.97 4876.95,2068.47 4900.13,2045.29 4900.13,1594.05 4884.13,1578.05 4884.13,1272.64 4885.27,1271.5 4885.27,1184.48 4814.04,1113.25 4304.74,1113.25 4273.74,1144.25 R214.1@4272.24,1144.25 R217.1@4347.04,1144.25
BOOT: C4.2 SW2.1 U1.27 | length 2087.3
  Top Layer w10: v2(2622.05,1929.13) 2624.34,1931.43 2624.34,1954.68 2613.78,1965.24 2613.78,2105.91 2681.1,2173.23 2681.1,2222.65 2669.31,2234.44 2547.2,2234.44 2516.48,2265.16 2516.48,2296.27 2522.92,2302.71 2597.54,2302.71 2603.98,2296.27 2603.98,2293.77 2629.12,2268.63 2680.37,2268.63 2742.11,2206.9 2784.05,2206.9 2818.07,2172.87 2818.07,2137.27 2845.3,2110.04 2900.37,2110.04 3010.83,2220.5 SW2.1@3010.83,2255.91 3003.93,2262.8 3003.93,2286.7 2947.25,2343.38 2947.25,2404.65 3066.1,2523.51 3112.62,2523.51 3154.9,2481.23 3154.9,2300.58 3199.57,2255.91 SW2.1@3241.14,2255.91 ; v2(2622.53,1857.32) 2622.53,1831.5 2623.11,1830.93 2623.11,1825.65 2631.83,1816.93 U1.27@2647.64,1816.93
  Bottom Layer w10: v2(2622.05,1929.13) 2622.29,1928.89 2622.29,1857.57 v2(2622.53,1857.32)
CAN_H: 100.1 J1.1 U100.7 | length 593.4
  Top Layer w15: J1.1@1808.9,2173.23 2003.94,2173.23 2044.49,2213.78 100.1@2117.43,2213.78 ; 100.1@2118.11,2213.78 2199.05,2213.78 2315.98,2330.71 U100.7@2337.73,2330.71
CAN_L: J1.2 R101.2 U100.6 | length 528.2
  Top Layer w15: J1.2@1822.53,2378.71 R101.2@2228.98,2378.71 2229.98,2379.71 2336.73,2379.71 U100.6@2337.73,2380.71
  Top Layer w30: J1.2@1813.9,2370.08 J1.2@1822.53,2378.71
